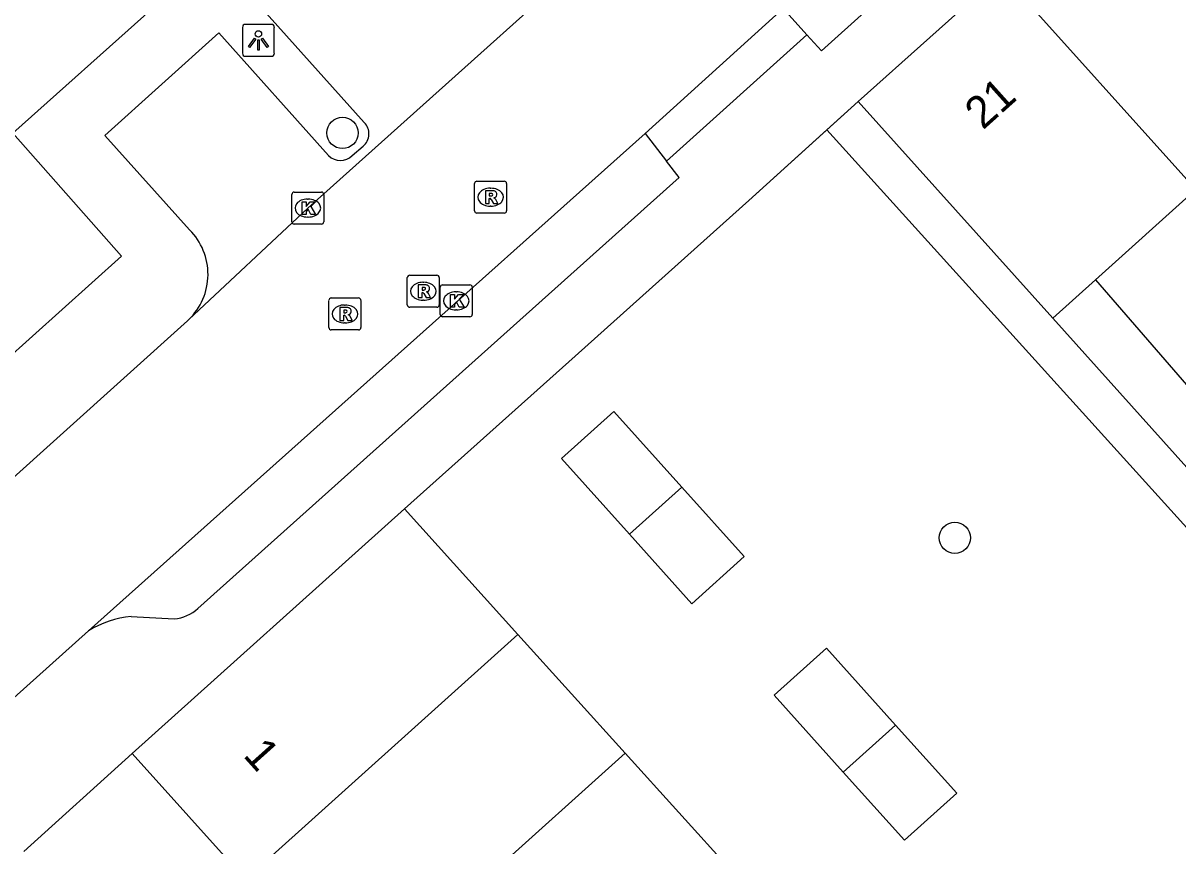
# Model space of a CAD drawing. Extents: x 162172 to 163187, y 382874 to 383684.
# Drawn here: x 162775.8 to 162811.9, y 383509.77 to 383535.51 of the extents above; entities that cross this region are included whole.
import ezdxf

# ---------------------------------------------------------------- set-up
doc = ezdxf.new("R2010")
doc.units = 0
for name, color, linetype in [('IMGEO_Boom', 7, 'Continuous'), ('IMGEO_Hek', 7, 'Continuous'), ('IMGEO_Kolk', 7, 'Continuous'), ('IMGEO_Lichtpunt', 7, 'Continuous'), ('IMGEO_Muur', 7, 'Continuous'), ('IMGEO_Pand', 7, 'Continuous'), ('IMGEO_Pand_nummerreeks', 7, 'Continuous'), ('IMGEO_Rijbaan_lokaal_open', 7, 'Continuous'), ('IMGEO_Rioolput', 7, 'Continuous'), ('IMGEO_Voetpad_open', 7, 'Continuous')]:
    doc.layers.add(name, color=color, linetype=linetype)

msp = doc.modelspace()

# ---------------------------------------------------------------- linework, layer by layer
at = {"layer": 'IMGEO_Boom'}
for centre in [(162785.781, 383532.069), (162804.923, 383519.406)]:
    msp.add_circle(centre, 0.489, dxfattribs=at)
at = {"layer": 'IMGEO_Hek'}
msp.add_lwpolyline([(162798.479, 383529.957), (162801.903, 383533.053)], dxfattribs=at)
at = {"layer": 'IMGEO_Kolk'}
for p, q in [((162784.197, 383529.294), (162784.197, 383530.146)), ((162784.272, 383530.22), (162785.124, 383530.22)), ((162785.198, 383530.146), (162785.198, 383529.294)), ((162784.685, 383530), (162784.71, 383530)), ((162784.708, 383529.44), (162784.683, 383529.44)), ((162785.124, 383529.22), (162784.272, 383529.22)), ((162788.836, 383526.392), (162788.836, 383527.244)), ((162788.911, 383527.318), (162789.763, 383527.318)), ((162789.837, 383527.244), (162789.837, 383526.392)), ((162789.324, 383527.098), (162789.349, 383527.098)), ((162789.347, 383526.538), (162789.322, 383526.538)), ((162789.763, 383526.318), (162788.911, 383526.318))]:
    msp.add_line(p, q, dxfattribs=at)
for points in [[(162784.197, 383529.294), (162784.197, 383530.146)], [(162784.272, 383530.22), (162785.124, 383530.22)], [(162785.198, 383530.146), (162785.198, 383529.294)], [(162784.518, 383529.92), (162784.641, 383529.92), (162784.641, 383529.769), (162784.771, 383529.92), (162784.935, 383529.92), (162784.789, 383529.769), (162784.942, 383529.52), (162784.79, 383529.52), (162784.705, 383529.684), (162784.641, 383529.617), (162784.641, 383529.52), (162784.518, 383529.52), (162784.518, 383529.92)], [(162785.124, 383529.22), (162784.272, 383529.22)], [(162788.836, 383526.392), (162788.836, 383527.244)], [(162788.911, 383527.318), (162789.763, 383527.318)], [(162789.837, 383527.244), (162789.837, 383526.392)], [(162789.157, 383527.018), (162789.28, 383527.018), (162789.28, 383526.867), (162789.41, 383527.018), (162789.574, 383527.018), (162789.428, 383526.867), (162789.581, 383526.618), (162789.429, 383526.618), (162789.344, 383526.782), (162789.28, 383526.715), (162789.28, 383526.618), (162789.157, 383526.618), (162789.157, 383527.018)], [(162789.763, 383526.318), (162788.911, 383526.318)]]:
    msp.add_lwpolyline(points, dxfattribs=at)
for centre, start, end in [((162784.274, 383530.144), 91.552, 178.448), ((162784.274, 383530.144), 91.552, 178.448), ((162785.122, 383530.144), 1.552, 88.448), ((162785.122, 383530.144), 1.552, 88.448), ((162784.274, 383529.296), 181.552, 268.448), ((162784.274, 383529.296), 181.552, 268.448), ((162785.122, 383529.296), 271.552, 358.448), ((162785.122, 383529.296), 271.552, 358.448), ((162788.913, 383527.242), 91.552, 178.448), ((162788.913, 383527.242), 91.552, 178.448), ((162789.761, 383527.242), 1.552, 88.448), ((162789.761, 383527.242), 1.552, 88.448), ((162788.913, 383526.394), 181.552, 268.448), ((162788.913, 383526.394), 181.552, 268.448), ((162789.761, 383526.394), 271.552, 358.448), ((162789.761, 383526.394), 271.552, 358.448)]:
    msp.add_arc(centre, 0.0765, start, end, dxfattribs=at)
for centre, major_axis, ratio, start_param, end_param in [((162784.684, 383529.72), (-0.387, 0.002), 0.722429, 4.712389, 7.853982), ((162784.709, 383529.72), (-0.39, 0.002), 0.717154, 1.570796, 4.712389), ((162789.323, 383526.818), (-0.387, 0.002), 0.722429, 4.712389, 7.853982), ((162789.348, 383526.818), (-0.39, 0.002), 0.717154, 1.570796, 4.712389)]:
    msp.add_ellipse(centre, major_axis=major_axis, ratio=ratio, start_param=start_param, end_param=end_param, dxfattribs=at)
at = {"layer": 'IMGEO_Lichtpunt'}
for p, q in [((162783.556, 383535.464), (162782.748, 383535.464)), ((162783.556, 383535.464), (162782.748, 383535.464)), ((162782.654, 383535.369), (162782.654, 383534.562)), ((162782.654, 383535.369), (162782.654, 383534.562)), ((162783.65, 383534.562), (162783.65, 383535.369)), ((162783.65, 383534.562), (162783.65, 383535.369)), ((162782.748, 383534.468), (162783.556, 383534.468)), ((162782.748, 383534.468), (162783.556, 383534.468))]:
    msp.add_line(p, q, dxfattribs=at)
for points in [[(162783.028, 383535.033), (162783.067, 383535.005), (162782.879, 383534.743), (162782.841, 383534.77), (162783.028, 383535.033)], [(162783.13, 383534.985), (162783.177, 383534.985), (162783.177, 383534.663), (162783.13, 383534.663), (162783.13, 383534.985)], [(162783.24, 383535.005), (162783.278, 383535.032), (162783.465, 383534.77), (162783.426, 383534.742), (162783.24, 383535.005)]]:
    msp.add_lwpolyline(points, dxfattribs=at)
msp.add_circle((162783.153, 383535.167), 0.0994, dxfattribs=at)
for centre, start, end in [((162782.748, 383535.369), 90, 180), ((162782.748, 383535.369), 90, 180), ((162783.556, 383535.369), 0, 90), ((162783.556, 383535.369), 0, 90), ((162782.748, 383534.562), 180, 270), ((162782.748, 383534.562), 180, 270), ((162783.556, 383534.562), 270, 0), ((162783.556, 383534.562), 270, 360)]:
    msp.add_arc(centre, 0.0946, start, end, dxfattribs=at)
at = {"layer": 'IMGEO_Muur'}
for points in [[(162798.479, 383529.957), (162792.856, 383524.915)], [(162787.715, 383520.314), (162792.856, 383524.915)]]:
    msp.add_lwpolyline(points, dxfattribs=at)
at = {"layer": 'IMGEO_Pand'}
for points in [[(162806.378, 383537.068), (162801.903, 383533.053)], [(162812.457, 383530.297), (162806.378, 383537.068)], [(162779.859, 383535.987), (162775.48, 383532.059)], [(162807.982, 383526.279), (162801.903, 383533.053)], [(162775.48, 383532.059), (162778.876, 383528.213), (162775.168, 383524.878)], [(162812.457, 383530.297), (162809.32, 383527.48)], [(162807.982, 383526.279), (162809.32, 383527.48)], [(162809.32, 383527.48), (162812.567, 383523.726), (162815.704, 383526.678), (162817.722, 383524.429), (162819.74, 383522.181)], [(162819.74, 383522.181), (162815.274, 383518.152), (162807.982, 383526.279)], [(162794.75, 383519.516), (162792.623, 383521.883), (162794.26, 383523.353), (162796.386, 383520.988)], [(162796.386, 383520.988), (162798.337, 383518.817), (162796.701, 383517.346), (162794.75, 383519.516)], [(162796.386, 383520.988), (162794.75, 383519.516)], [(162787.715, 383520.314), (162779.209, 383512.659)], [(162787.715, 383520.314), (162791.267, 383516.381)], [(162782.753, 383508.717), (162791.267, 383516.381)], [(162791.267, 383516.381), (162794.618, 383512.67)], [(162801.435, 383512.079), (162799.275, 383514.483), (162800.911, 383515.953), (162803.07, 383513.551)], [(162803.07, 383513.551), (162804.989, 383511.417), (162803.352, 383509.946), (162801.435, 383512.079)], [(162801.435, 383512.079), (162803.07, 383513.551)], [(162779.209, 383512.659), (162782.753, 383508.717)], [(162786.095, 383504.999), (162794.618, 383512.67)], [(162794.618, 383512.67), (162797.969, 383508.959)]]:
    msp.add_lwpolyline(points, dxfattribs=at)
at = {"layer": 'IMGEO_Rijbaan_lokaal_open'}
for points in [[(162821.053, 383562.317), (162784.698, 383529.72), (162780.973, 383526.23)], [(162795.243, 383532.05), (162799.554, 383535.964)], [(162777.843, 383516.5), (162795.243, 383532.05)], [(162771.287, 383517.512), (162780.938, 383526.198), (162780.973, 383526.23)], [(162774.683, 383513.676), (162777.843, 383516.5)]]:
    msp.add_lwpolyline(points, dxfattribs=at)
at = {"layer": 'IMGEO_Rioolput'}
for p, q in [((162789.91, 383529.634), (162789.91, 383530.486)), ((162789.985, 383530.56), (162790.837, 383530.56)), ((162790.911, 383530.486), (162790.911, 383529.634)), ((162790.398, 383530.34), (162790.423, 383530.34)), ((162790.421, 383529.78), (162790.396, 383529.78)), ((162790.837, 383529.56), (162789.985, 383529.56)), ((162787.807, 383526.692), (162787.807, 383527.544)), ((162787.882, 383527.618), (162788.734, 383527.618)), ((162788.808, 383527.544), (162788.808, 383526.692)), ((162788.295, 383527.398), (162788.32, 383527.398)), ((162785.357, 383525.982), (162785.357, 383526.834)), ((162785.432, 383526.908), (162786.284, 383526.908)), ((162786.358, 383526.834), (162786.358, 383525.982)), ((162788.318, 383526.838), (162788.293, 383526.838)), ((162785.845, 383526.688), (162785.87, 383526.688)), ((162788.734, 383526.618), (162787.882, 383526.618)), ((162785.868, 383526.128), (162785.843, 383526.128)), ((162786.284, 383525.908), (162785.432, 383525.908))]:
    msp.add_line(p, q, dxfattribs=at)
for points in [[(162789.91, 383529.634), (162789.91, 383530.486)], [(162789.985, 383530.56), (162790.837, 383530.56)], [(162790.911, 383530.486), (162790.911, 383529.634)], [(162790.499, 383530.258), (162790.247, 383530.26), (162790.247, 383529.86)], [(162790.247, 383529.86), (162790.371, 383529.86), (162790.371, 383530.022), (162790.382, 383530.022)], [(162790.425, 383530.179), (162790.371, 383530.179), (162790.371, 383530.098)], [(162790.371, 383530.098), (162790.423, 383530.098)], [(162790.429, 383529.993), (162790.5, 383529.86), (162790.64, 383529.86), (162790.575, 383529.986)], [(162790.837, 383529.56), (162789.985, 383529.56)], [(162787.807, 383526.692), (162787.807, 383527.544)], [(162787.882, 383527.618), (162788.734, 383527.618)], [(162788.808, 383527.544), (162788.808, 383526.692)], [(162788.396, 383527.316), (162788.144, 383527.318), (162788.144, 383526.918)], [(162788.322, 383527.237), (162788.268, 383527.237), (162788.268, 383527.156)], [(162788.268, 383527.156), (162788.32, 383527.156)], [(162785.357, 383525.982), (162785.357, 383526.834)], [(162785.432, 383526.908), (162786.284, 383526.908)], [(162786.358, 383526.834), (162786.358, 383525.982)], [(162788.144, 383526.918), (162788.268, 383526.918), (162788.268, 383527.08), (162788.279, 383527.08)], [(162788.326, 383527.051), (162788.397, 383526.918), (162788.537, 383526.918), (162788.472, 383527.044)], [(162785.946, 383526.606), (162785.694, 383526.608), (162785.694, 383526.208)], [(162785.872, 383526.527), (162785.818, 383526.527), (162785.818, 383526.446)], [(162785.818, 383526.446), (162785.87, 383526.446)], [(162788.734, 383526.618), (162787.882, 383526.618)], [(162785.694, 383526.208), (162785.818, 383526.208), (162785.818, 383526.37), (162785.829, 383526.37)], [(162785.876, 383526.341), (162785.947, 383526.208), (162786.087, 383526.208), (162786.022, 383526.334)], [(162786.284, 383525.908), (162785.432, 383525.908)]]:
    msp.add_lwpolyline(points, dxfattribs=at)
for centre, radius, start, end in [((162789.987, 383530.484), 0.0765, 91.552, 178.448), ((162789.987, 383530.484), 0.0765, 91.552, 178.448), ((162790.835, 383530.484), 0.0765, 1.552, 88.448), ((162790.835, 383530.484), 0.0765, 1.552, 88.448), ((162790.381, 383529.969), 0.0533, 26.0293, 88.6989), ((162790.407, 383530.287), 0.19, 274.7715, 282.9687), ((162790.431, 383530.083), 0.0964, 77.0061, 93.1865), ((162790.445, 383530.14), 0.0378, 276.6634, 79.6772), ((162790.498, 383530.148), 0.109, 350.3612, 89.416), ((162790.496, 383530.148), 0.112, 277.5842, 350.9817), ((162790.48, 383529.933), 0.108, 29.5134, 73.7905), ((162789.987, 383529.636), 0.0765, 181.552, 268.448), ((162789.987, 383529.636), 0.0765, 181.552, 268.448), ((162790.835, 383529.636), 0.0765, 271.552, 358.448), ((162790.835, 383529.636), 0.0765, 271.552, 358.448), ((162787.884, 383527.542), 0.0765, 91.552, 178.448), ((162787.884, 383527.542), 0.0765, 91.552, 178.448), ((162788.732, 383527.542), 0.0765, 1.552, 88.448), ((162788.732, 383527.542), 0.0765, 1.552, 88.448), ((162788.304, 383527.345), 0.19, 274.7715, 282.9687), ((162788.328, 383527.141), 0.0964, 77.0061, 93.1865), ((162788.342, 383527.198), 0.0378, 276.6634, 79.6772), ((162788.395, 383527.206), 0.109, 350.3612, 89.416), ((162788.393, 383527.206), 0.112, 277.5842, 350.9817), ((162785.434, 383526.832), 0.0765, 91.552, 178.448), ((162785.434, 383526.832), 0.0765, 91.552, 178.448), ((162786.282, 383526.832), 0.0765, 1.552, 88.448), ((162786.282, 383526.832), 0.0765, 1.552, 88.448), ((162788.278, 383527.027), 0.0533, 26.0293, 88.6989), ((162788.377, 383526.991), 0.108, 29.5134, 73.7905), ((162785.854, 383526.635), 0.19, 274.7715, 282.9687), ((162785.878, 383526.431), 0.0964, 77.0061, 93.1865), ((162785.892, 383526.488), 0.0378, 276.6634, 79.6772), ((162785.945, 383526.496), 0.109, 350.3612, 89.416), ((162785.943, 383526.496), 0.112, 277.5842, 350.9817), ((162787.884, 383526.694), 0.0765, 181.552, 268.448), ((162787.884, 383526.694), 0.0765, 181.552, 268.448), ((162788.732, 383526.694), 0.0765, 271.552, 358.448), ((162788.732, 383526.694), 0.0765, 271.552, 358.448), ((162785.828, 383526.317), 0.0533, 26.0293, 88.6989), ((162785.927, 383526.281), 0.108, 29.5134, 73.7905), ((162785.434, 383525.984), 0.0765, 181.552, 268.448), ((162785.434, 383525.984), 0.0765, 181.552, 268.448), ((162786.282, 383525.984), 0.0765, 271.552, 358.448), ((162786.282, 383525.984), 0.0765, 271.552, 358.448)]:
    msp.add_arc(centre, radius, start, end, dxfattribs=at)
for centre, major_axis, ratio, start_param, end_param in [((162790.397, 383530.06), (-0.387, 0.002), 0.722429, 4.712389, 7.853982), ((162790.422, 383530.06), (-0.39, 0.002), 0.717154, 1.570796, 4.712389), ((162788.294, 383527.118), (-0.387, 0.002), 0.722429, 4.712389, 7.853982), ((162788.319, 383527.118), (-0.39, 0.002), 0.717154, 1.570796, 4.712389), ((162785.844, 383526.408), (-0.387, 0.002), 0.722429, 4.712389, 7.853982), ((162785.869, 383526.408), (-0.39, 0.002), 0.717154, 1.570796, 4.712389)]:
    msp.add_ellipse(centre, major_axis=major_axis, ratio=ratio, start_param=start_param, end_param=end_param, dxfattribs=at)
at = {"layer": 'IMGEO_Voetpad_open'}
for points in [[(162786.462, 383532.399), (162783.04, 383536.211), (162790.332, 383542.763), (162793.768, 383538.905)], [(162800.294, 383535.139), (162800.757, 383534.637), (162805.097, 383538.559), (162804.426, 383539.325)], [(162799.554, 383535.964), (162800.294, 383535.139)], [(162780.999, 383529.04), (162778.348, 383531.992), (162781.911, 383535.2), (162785.343, 383531.36)], [(162795.911, 383531.186), (162800.294, 383535.139)], [(162801.903, 383533.053), (162800.917, 383532.162)], [(162800.917, 383532.162), (162798.479, 383529.957), (162792.856, 383524.915), (162787.715, 383520.314)], [(162795.243, 383532.05), (162795.911, 383531.186)], [(162829.409, 383500.736), (162825.19, 383505.317), (162800.917, 383532.162)], [(162786.088, 383531.359), (162786.424, 383531.651)], [(162781.26, 383517.197), (162796.308, 383530.672), (162795.911, 383531.186)], [(162779.174, 383516.948), (162780.52, 383516.875)], [(162779.209, 383512.659), (162775.823, 383509.594)]]:
    msp.add_lwpolyline(points, dxfattribs=at)
for centre, radius, start, end in [((162786.095, 383532.043), 0.511, 309.9975, 44.186), ((162785.716, 383531.742), 0.534, 225.6587, 314.1875), ((162779.611, 383527.648), 1.966, 313.843, 45.0968), ((162780.439, 383518.073), 1.2, 273.8719, 313.1592), ((162779.505, 383513.763), 3.202, 95.9338, 121.2715)]:
    msp.add_arc(centre, radius, start, end, dxfattribs=at)

# ---------------------------------------------------------------- texts
at = {"layer": 'IMGEO_Pand_nummerreeks'}
for s, rotation, p in [('21', 41.9013, (162805.8, 383532.144)), ('1', 311.8929, (162782.648, 383512.589))]:
    msp.add_text(s, height=1, rotation=rotation, dxfattribs=at).set_placement(p)

doc.saveas('drawing.dxf')
